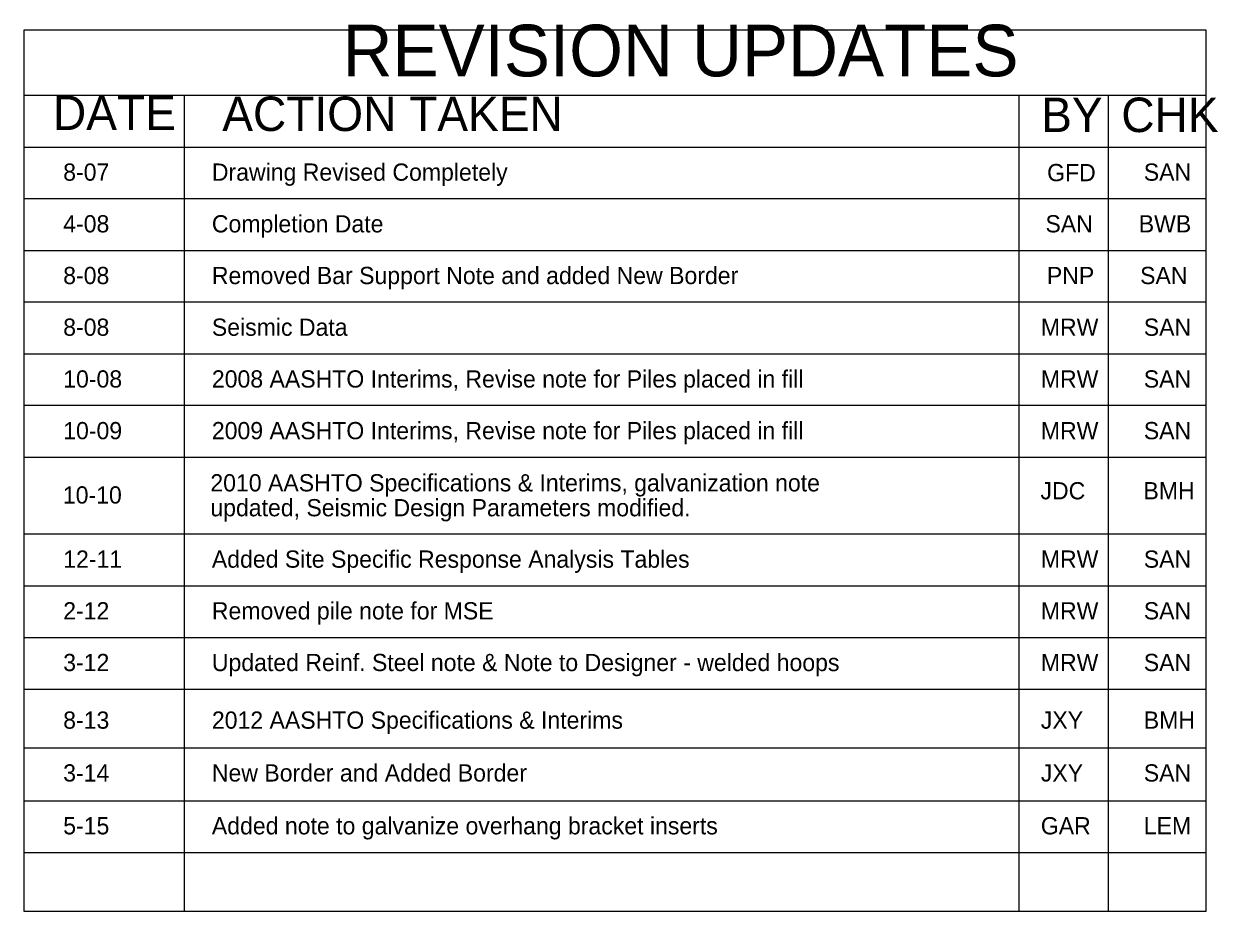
# Model space of a CAD drawing. Extents: x -1.3 to 94.5, y -4.9 to 22.8.
# Drawn here: x 77.17 to 94.5, y -4.91 to 7.97 of the extents above; entities that cross this region are included whole.
import ezdxf

# ---------------------------------------------------------------- set-up
doc = ezdxf.new("R2010")
doc.units = 0
doc.layers.add('BR_BORDER LINES', color=7, linetype='Continuous')
doc.layers.add('BR_TEXT', color=7, linetype='Continuous')

msp = doc.modelspace()

# ---------------------------------------------------------------- linework, layer by layer
at = {"layer": 'BR_BORDER LINES'}
for p, q in [((94.325, 7.877), (77.169, 7.877)), ((77.169, 7.877), (77.169, -2.536)), ((94.325, -2.536), (94.325, 7.877)), ((77.169, 6.931), (94.325, 6.931)), ((79.496, 6.931), (79.496, -2.531)), ((91.611, -2.536), (91.611, 6.931)), ((92.904, 6.931), (92.904, -2.537)), ((77.169, 6.181), (94.325, 6.181)), ((94.325, 5.431), (77.169, 5.431)), ((77.169, 4.681), (94.325, 4.681)), ((94.325, 3.93), (77.169, 3.93)), ((77.169, 3.18), (94.325, 3.18)), ((94.325, 2.43), (77.169, 2.43)), ((77.169, 1.68), (94.325, 1.68)), ((94.325, 0.566), (77.169, 0.566)), ((77.169, -0.184), (94.325, -0.184)), ((77.169, -0.934), (94.325, -0.934)), ((77.169, -1.684), (94.325, -1.684)), ((77.169, -2.536), (94.325, -2.536)), ((77.169, -2.536), (77.169, -4.905)), ((79.496, -2.536), (79.496, -4.899)), ((91.611, -4.905), (91.611, -2.536)), ((92.904, -2.536), (92.904, -4.905)), ((94.325, -4.905), (94.325, -2.536)), ((77.169, -3.303), (94.325, -3.303)), ((77.169, -4.053), (94.325, -4.053)), ((77.169, -4.905), (94.325, -4.905))]:
    msp.add_line(p, q, dxfattribs=at)

# ---------------------------------------------------------------- texts
at = {"layer": 'BR_TEXT'}
for s, height, p in [('REVISION UPDATES', 0.75, (81.793, 7.206)), ('DATE', 0.5, (77.591, 6.428)), ('ACTION TAKEN', 0.5, (80.048, 6.413)), ('BY', 0.5, (91.93, 6.398)), ('CHK', 0.5, (93.093, 6.398)), ('8-07', 0.25, (77.74, 5.692)), ('Drawing Revised Completely', 0.25, (79.897, 5.692)), ('GFD', 0.25, (92.016, 5.685)), ('SAN', 0.25, (93.419, 5.692)), ('Completion Date', 0.25, (79.897, 4.942)), ('4-08', 0.25, (77.74, 4.942)), ('SAN', 0.25, (91.992, 4.942)), ('BWB', 0.25, (93.346, 4.942)), ('8-08 ', 0.25, (77.74, 4.192)), ('Removed Bar Support Note and added New Border', 0.25, (79.897, 4.192)), ('PNP', 0.25, (92.013, 4.192)), ('SAN', 0.25, (93.366, 4.192)), ('8-08', 0.25, (77.74, 3.442)), ('Seismic Data', 0.25, (79.897, 3.442)), ('MRW', 0.25, (91.925, 3.442)), ('SAN', 0.25, (93.419, 3.442)), ('2008 AASHTO Interims, Revise note for Piles placed in fill', 0.25, (79.897, 2.691)), ('10-08', 0.25, (77.74, 2.691)), ('MRW', 0.25, (91.925, 2.691)), ('SAN', 0.25, (93.419, 2.691)), ('10-09', 0.25, (77.74, 1.941)), ('2009 AASHTO Interims, Revise note for Piles placed in fill', 0.25, (79.897, 1.941)), ('MRW', 0.25, (91.925, 1.941)), ('SAN', 0.25, (93.419, 1.941)), ('2010 AASHTO Specifications & Interims, galvanization note', 0.25, (79.875, 1.184)), ('10-10', 0.25, (77.735, 1.008)), ('JDC', 0.25, (91.92, 1.069)), ('BMH', 0.25, (93.414, 1.069)), ('updated, Seismic Design Parameters modified. ', 0.25, (79.875, 0.823)), ('12-11', 0.25, (77.74, 0.077)), ('Added Site Specific Response Analysis Tables', 0.25, (79.897, 0.077)), ('MRW', 0.25, (91.925, 0.077)), ('SAN', 0.25, (93.419, 0.077)), ('2-12', 0.25, (77.74, -0.673)), ('Removed pile note for MSE', 0.25, (79.897, -0.673)), ('MRW', 0.25, (91.925, -0.673)), ('SAN', 0.25, (93.419, -0.673)), ('3-12', 0.25, (77.74, -1.423)), ('Updated Reinf. Steel note & Note to Designer - welded hoops', 0.25, (79.897, -1.423)), ('MRW', 0.25, (91.925, -1.423)), ('SAN', 0.25, (93.419, -1.423)), ('8-13', 0.25, (77.74, -2.259)), ('2012 AASHTO Specifications & Interims', 0.25, (79.897, -2.259)), ('JXY', 0.25, (91.925, -2.259)), ('BMH', 0.25, (93.419, -2.259)), ('3-14', 0.25, (77.74, -3.025)), ('New Border and Added Border', 0.25, (79.897, -3.025)), ('SAN', 0.25, (93.419, -3.025)), ('JXY', 0.25, (91.925, -3.025)), ('5-15', 0.25, (77.74, -3.792)), ('Added note to galvanize overhang bracket inserts', 0.25, (79.897, -3.792)), ('GAR', 0.25, (91.925, -3.792)), ('LEM', 0.25, (93.419, -3.792))]:
    msp.add_text(s, height=height, dxfattribs=at).set_placement(p)

doc.saveas('drawing.dxf')
